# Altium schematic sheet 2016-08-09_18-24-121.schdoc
size 328 x 139 mm; SheetNumber: 1; SheetTotal: 1
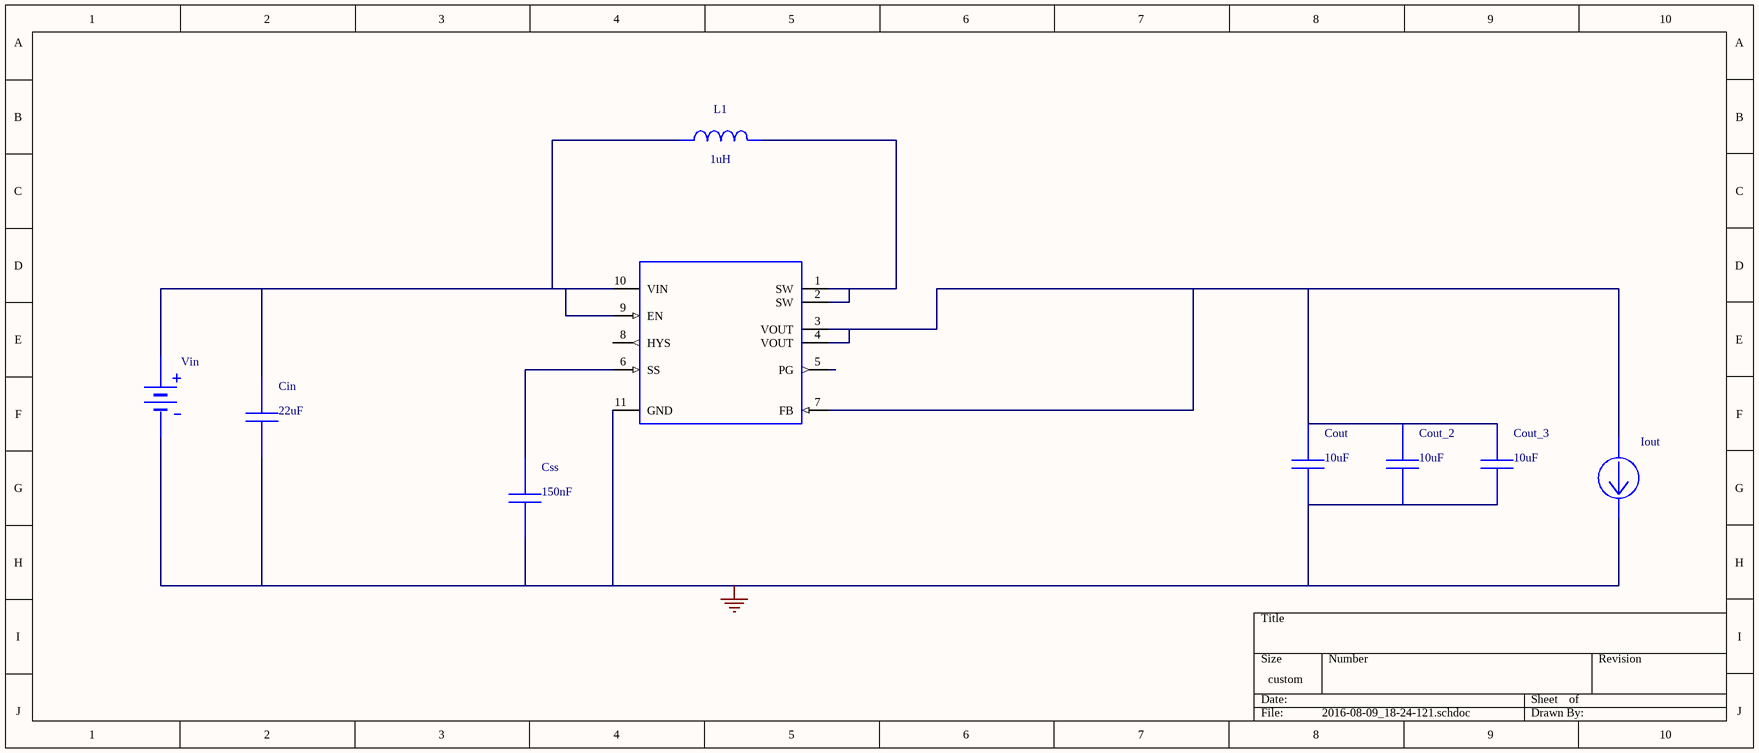
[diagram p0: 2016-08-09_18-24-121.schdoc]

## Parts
Cin  value 22uF  (hidden comment: LMK212BJ226MG-T)
Cout  value 10uF  (hidden comment: LMK212BJ106KG-T)
Cout_2  value 10uF  (hidden comment: LMK212BJ106KG-T)
Cout_3  value 10uF  (hidden comment: LMK212BJ106KG-T)
Css  value 150nF  (hidden comment: GRM155R61A154KE19D)
Iout  WB_CURRENT_LOAD  (value not drawn)
L1  value 1uH  (hidden comment: SRU1028-1R0Y)
U1  TPS61232DRCR  (value not drawn)
Vin  WB_BATTERY  (value not drawn)

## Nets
0: Cin.2 Cout.2 Cout_2.2 Cout_3.2 Css.2 Iout.2(-) U1.11(GND) Vin.2(-)
NetCin_1: Cin.1 L1.1 U1.9(EN) U1.10(VIN) Vin.1(+)
NetCout_1: Cout.1 Cout_2.1 Cout_3.1 Iout.1(+) U1.3(VOUT) U1.4(VOUT) U1.7(FB)
NetCss_1: Css.1 U1.6(SS)
NetL1_2: L1.2 U1.1(SW) U1.2(SW)

Not connected (* = marked no-connect by the designer): U1 5(PG) 8(HYS)

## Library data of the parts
Cin = LMK212BJ226MG-T: Manufacturer Name: Taiyo Yuden
Cout Cout_2 Cout_3 = LMK212BJ106KG-T: Manufacturer Name: Taiyo Yuden
Css = GRM155R61A154KE19D: GRM155R61A154KE1; Manufacturer Name: MuRata
L1 = SRU1028-1R0Y: Manufacturer Name: Bourns
U1 = TPS61232DRCR: Manufacturer Name: Texas Instruments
